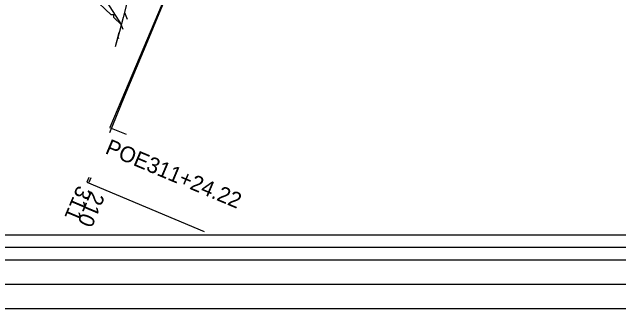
# Model space of a CAD drawing. Extents: x 11779 to 13421, y 9945 to 11090.
# Drawn here: x 12270.4 to 12756.9, y 9944.8 to 10182.8 of the extents above; entities that cross this region are included whole.
import ezdxf

# ---------------------------------------------------------------- set-up
doc = ezdxf.new("R2010")
doc.units = 0
for name, color, linetype in [('Default', 7, 'Continuous'), ('R_Horz Alg', 7, 'Continuous'), ('R_Horz Alg Annot', 7, 'Continuous'), ('S_PAVEMENT_CROWN', 7, 'Continuous')]:
    doc.layers.add(name, color=color, linetype=linetype)

msp = doc.modelspace()

# ---------------------------------------------------------------- linework, layer by layer
at = {"layer": 'Default'}
for p, q in [((12332.57, 10212.64), (12357.92, 10172.99)), ((12349.79, 10180.7), (12323.77, 10205.39)), ((12362.49, 10189.93), (12359.44, 10178.64)), ((12360.52, 10182.54), (12362.07, 10178.5)), ((12352.11, 10180.7), (12349.79, 10180.7)), ((12352.11, 10178.5), (12352.11, 10180.7)), ((12357.92, 10172.99), (12352.11, 10178.5)), ((12359.44, 10178.64), (12356.4, 10167.34)), ((12362.07, 10178.5), (12362.57, 10177.19)), ((12357.64, 10173.29), (12359.2, 10169.25)), ((12356.4, 10167.34), (12353.35, 10156.05)), ((12356.1, 10166.26), (12353.06, 10154.96)), ((12355.12, 10163.05), (12355.69, 10161.55)), ((13397.74, 10003.88), (11816.83, 10003.88)), ((11783.99, 9984.17), (13420.77, 9984.17)), ((11783.99, 9964.48), (13420.77, 9964.48)), ((13420.77, 9944.79), (11783.99, 9944.79))]:
    msp.add_line(p, q, dxfattribs=at)
msp.add_lwpolyline([(11809.67, 11038.21), (13405.96, 11038.21), (13405.96, 9994.1), (11809.67, 9994.1)], close=True, dxfattribs=at)
at = {"layer": 'R_Horz Alg'}
for points in [[(12362.02, 10084.54), (12348.77, 10090.12)], [(12330.34, 10046.42), (12424.42, 10006.81)]]:
    msp.add_lwpolyline(points, dxfattribs=at)
at = {"layer": 'R_Horz Alg Annot'}
for p, q in [((12561.18, 10594.64), (12348.77, 10090.19)), ((12561.18, 10594.64), (12348.77, 10090.19)), ((12331.9, 10050.11), (12330.34, 10046.42)), ((12331.9, 10050.11), (12330.34, 10046.42))]:
    msp.add_line(p, q, dxfattribs=at)
at = {"layer": 'S_PAVEMENT_CROWN'}
for points in [[(12348.77, 10086.4), (12351.19, 10092.23), (12360.66, 10115.16), (12370.13, 10138.08), (12379.19, 10159.93), (12388.24, 10181.78), (12397.3, 10203.62), (12406.35, 10225.47), (12417.01, 10250.93), (12427.67, 10276.38), (12438.33, 10301.84), (12448.99, 10327.29), (12465.72, 10366.99), (12482.44, 10406.69), (12498.83, 10445.7), (12515.22, 10484.7), (12524.08, 10505.58), (12532.93, 10526.45), (12541.79, 10547.32), (12550.64, 10568.19), (12568.25, 10609.58), (12585.85, 10650.97)], [(12348.77, 10086.4), (12351.19, 10092.23), (12360.66, 10115.16), (12370.13, 10138.08), (12379.19, 10159.93), (12388.24, 10181.78), (12397.3, 10203.62), (12406.35, 10225.47), (12417.01, 10250.93), (12427.67, 10276.38), (12438.33, 10301.84), (12448.99, 10327.29), (12465.72, 10366.99), (12482.44, 10406.69), (12498.83, 10445.7), (12515.22, 10484.7), (12524.08, 10505.58), (12532.93, 10526.45), (12541.79, 10547.32), (12550.64, 10568.19), (12568.25, 10609.58), (12585.85, 10650.97)], [(12332.24, 10046.38), (12333.78, 10050.11)], [(12332.24, 10046.38), (12333.78, 10050.11)]]:
    msp.add_lwpolyline(points, dxfattribs=at)

# ---------------------------------------------------------------- texts
at = {"layer": 'R_Horz Alg Annot'}
for s, rotation, p in [('POE311+24.22', 337.208, (12344.26, 10069.78)), ('311', 247.208, (12323.02, 10044.53)), ('210', 247.1659, (12333.48, 10039.91))]:
    msp.add_text(s, height=12.6, rotation=rotation, dxfattribs=at).set_placement(p)

doc.saveas('drawing.dxf')
